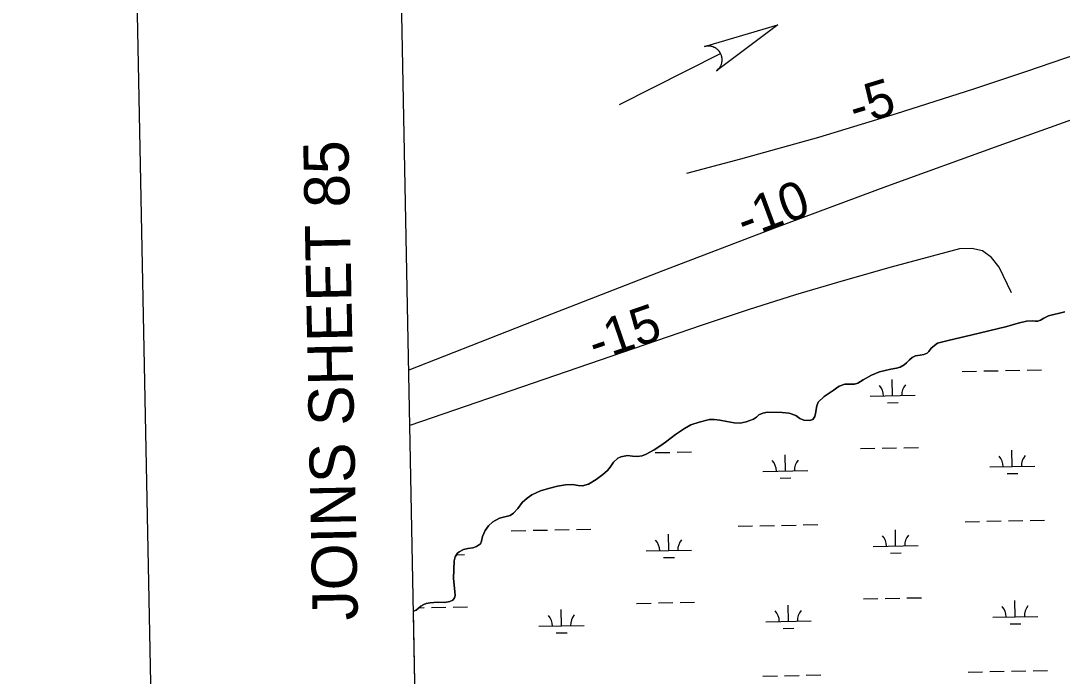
# Model space of a CAD drawing. Extents: x 3989314 to 4027622, y 243956 to 270014.
# Drawn here: x 3992659 to 3994963, y 253743 to 255194 of the extents above; entities that cross this region are included whole.
import ezdxf

# ---------------------------------------------------------------- set-up
doc = ezdxf.new("R2010")
doc.units = 0
for name, color, linetype in [('V-ANNO-SYMB', 7, 'Continuous'), ('V-ANNO-TEXT', 7, 'Continuous'), ('V-GRID-FRAM', 7, 'Continuous'), ('V-RIVR-EDGE', 7, 'Continuous'), ('V-STRM-FLOW', 7, 'Continuous'), ('V-TOPO-MINR', 7, 'Continuous'), ('V-TOPO-MINR-IDEN', 7, 'Continuous'), ('V-WETL-SWMP', 7, 'Continuous')]:
    doc.layers.add(name, color=color, linetype=linetype)

msp = doc.modelspace()

# ---------------------------------------------------------------- linework, layer by layer
at = {"layer": 'V-ANNO-SYMB'}
msp.add_lwpolyline([(3993116.1, 245218.5), (4026192.7, 245877.7), (4025736.1, 268789.7), (3992659.5, 268130.6), (3993116.1, 245218.5)], dxfattribs=at)
at = {"layer": 'V-GRID-FRAM'}
msp.add_lwpolyline([(3993261.4, 267575.2), (4025156.8, 268210.8), (4025527.1, 250031.9), (3993615.7, 249396), (3993261.4, 267575.2)], dxfattribs=at)
at = {"layer": 'V-RIVR-EDGE'}
for points in [[(3994968.3, 254550), (3994932.8, 254540.7), (3994922.1, 254535.7), (3994914.7, 254531.5), (3994909.2, 254529.1), (3994902.6, 254528.9), (3994897.1, 254529.5), (3994884.1, 254529.1), (3994865.7, 254524.3), (3994840.5, 254517.1), (3994761, 254498.4), (3994713.6, 254486.7), (3994687.2, 254480.5), (3994672.9, 254469.6), (3994667.4, 254461.6), (3994664.4, 254458.4), (3994656.7, 254455), (3994648.7, 254454), (3994638.6, 254452.2), (3994630.8, 254448.8)], [(3994630.8, 254448.8), (3994624.7, 254443.6), (3994618.2, 254436.6), (3994613.2, 254432.3), (3994604.1, 254427.3), (3994596.5, 254424.9), (3994583.6, 254423), (3994558.6, 254417.2), (3994541.3, 254409.4), (3994522.5, 254398.9), (3994510.8, 254391.9), (3994503, 254389.5), (3994491.5, 254389.4), (3994481.8, 254389.6), (3994469.1, 254385), (3994456.2, 254375.8), (3994436, 254362.7), (3994422.9, 254349.5), (3994420.1, 254342), (3994417.4, 254325.1), (3994415.4, 254318.1), (3994411.3, 254311.8), (3994403.5, 254309), (3994391.6, 254310.3), (3994382.8, 254313.9), (3994373.5, 254320.2), (3994359, 254325.5), (3994343.1, 254327.3), (3994311.1, 254327.6), (3994300.4, 254325.6), (3994291.8, 254321.8), (3994286.7, 254317), (3994279.7, 254312), (3994264.1, 254306.2), (3994250.6, 254303.6), (3994237.2, 254303.8), (3994221.1, 254306.9), (3994205.4, 254310.3), (3994193.1, 254311.8), (3994182.4, 254311.4), (3994159.8, 254305.8), (3994141.1, 254299.4), (3994127.2, 254291.4), (3994107.6, 254278.2), (3994088.5, 254263.7), (3994077.6, 254255.1), (3994060.6, 254244.1), (3994042.9, 254234.6), (3994033.6, 254231.4), (3994022.9, 254229.3), (3994012.5, 254230.3), (3994001.2, 254231.7), (3993986.9, 254229.2), (3993980, 254226.1), (3993970.4, 254217.1), (3993963.3, 254205.7), (3993957.2, 254198.4), (3993947.1, 254189.6), (3993932.2, 254179), (3993914.7, 254168.7), (3993902, 254164.7), (3993892.3, 254165.2), (3993879.4, 254167.4), (3993863.9, 254166.8), (3993846.2, 254164.1), (3993826.4, 254158.5), (3993808.9, 254153.3), (3993789.8, 254145.1), (3993779.1, 254137.7), (3993768, 254127.6), (3993758.9, 254114.8), (3993749, 254104.1), (3993741.5, 254099.3), (3993732.9, 254096.5), (3993718.4, 254093.1), (3993703.6, 254084.7), (3993693.8, 254076.3), (3993686.3, 254065.8), (3993680.8, 254052.5), (3993678.6, 254041.9), (3993675.9, 254036), (3993667.1, 254030.4), (3993659.2, 254027.4), (3993648.1, 254026), (3993638.6, 254023.8), (3993628.8, 254018.4), (3993625.1, 254015.4), (3993620.3, 254007.8), (3993618, 253998.7), (3993616.7, 253959.3), (3993619.5, 253930.7), (3993619.9, 253922.2), (3993618.8, 253917.2), (3993615, 253911.8), (3993608.6, 253908.7), (3993596.7, 253906.8), (3993580.8, 253907), (3993564.7, 253905.8)], [(3993564.7, 253905.8), (3993556, 253904.1), (3993550.8, 253902.1), (3993544.1, 253898.4), (3993533.8, 253889.6), (3993528.2, 253887)]]:
    msp.add_lwpolyline(points, dxfattribs=at)
at = {"layer": 'V-STRM-FLOW'}
msp.add_line((3993983.9, 255008.2), (3994207.3, 255121.2), dxfattribs=at)
msp.add_lwpolyline([(3994171.5, 255136.7), (3994333.7, 255185.1), (3994198.5, 255083.1), (3994200.9, 255085.1), (3994202.9, 255087.2), (3994203.7, 255088.1), (3994204.3, 255088.9), (3994205.1, 255089.9), (3994205.8, 255090.9), (3994206.3, 255091.8), (3994207, 255093.1), (3994207.7, 255094.5), (3994208.1, 255095.3), (3994208.5, 255096.3), (3994209, 255097.7), (3994209.4, 255098.8), (3994209.7, 255100), (3994209.9, 255100.8), (3994210, 255101.6), (3994210.2, 255102.7), (3994210.4, 255103.7), (3994210.5, 255104.7), (3994210.5, 255105.5), (3994210.6, 255106.7), (3994210.6, 255107.9), (3994210.6, 255108.9), (3994210.5, 255110), (3994210.4, 255110.9), (3994210.3, 255111.7), (3994210.2, 255112.4), (3994210, 255113.4), (3994209.8, 255114.4), (3994209.5, 255115.3), (3994209.3, 255116.3), (3994209, 255117.2), (3994208.6, 255118.1), (3994208.3, 255118.9), (3994207.9, 255120), (3994207.3, 255121.2), (3994207.1, 255121.5), (3994206.8, 255122.1), (3994206.5, 255122.7), (3994206.1, 255123.3), (3994205.7, 255123.9), (3994205.4, 255124.5), (3994204.9, 255125.1), (3994204.6, 255125.6), (3994204.1, 255126.2), (3994203.6, 255126.8), (3994203.3, 255127.2), (3994202.4, 255128.2), (3994201.9, 255128.7), (3994201.5, 255129.1), (3994201, 255129.7), (3994200.4, 255130.1), (3994199.8, 255130.6), (3994199.1, 255131.2), (3994198.5, 255131.7), (3994198, 255132.1), (3994197.5, 255132.4), (3994196.9, 255132.9), (3994196.3, 255133.2), (3994195.6, 255133.7), (3994194.9, 255134.1), (3994194.2, 255134.4), (3994193.3, 255134.9), (3994192.6, 255135.2), (3994191.8, 255135.5), (3994191.1, 255135.8), (3994190.5, 255136.1), (3994189.8, 255136.3), (3994188.8, 255136.6), (3994188.8, 255136.6), (3994188.2, 255136.8), (3994187.8, 255136.9), (3994187.1, 255137.1), (3994186.2, 255137.3), (3994185.6, 255137.4), (3994185, 255137.5), (3994184.2, 255137.6), (3994183.4, 255137.7), (3994182.9, 255137.8), (3994182.2, 255137.8), (3994181.2, 255137.9), (3994180.6, 255137.9), (3994180.2, 255137.9), (3994179.8, 255137.9), (3994179.3, 255137.9), (3994178.6, 255137.9), (3994178, 255137.8), (3994177.3, 255137.8), (3994176.7, 255137.7), (3994175.9, 255137.6), (3994175.4, 255137.5), (3994174.6, 255137.4), (3994173.7, 255137.2), (3994173, 255137.1), (3994172.5, 255136.9), (3994172, 255136.8), (3994171.7, 255136.7)], close=True, dxfattribs=at)
at = {"layer": 'V-TOPO-MINR'}
for points in [[(3995631.1, 255198.8), (3995607.7, 255193.4), (3995584.5, 255187.4), (3995561.5, 255180.4), (3995538.8, 255172.8), (3994822.5, 254916.8), (3994574, 254826.7), (3994326.2, 254734.9), (3994079.4, 254640.7), (3993833.1, 254544.8), (3993517.8, 254420.3)], [(3995216.6, 255200.1), (3995106.4, 255159), (3994995.5, 255119.7), (3994884.1, 255081.6), (3994766.6, 255042.5), (3994595.6, 254987.8), (3994423.9, 254935.7), (3994251, 254887.5), (3994131.6, 254856.1)], [(3994850.6, 254591.8), (3994823.4, 254648.6), (3994806.6, 254669.9), (3994786.8, 254684.8), (3994762.6, 254690.1), (3994735.5, 254689.1), (3994584.1, 254648.2), (3994478.4, 254618.5), (3994373, 254587.4), (3994268.3, 254554.1), (3994164.1, 254519.5), (3993520.2, 254298.3)]]:
    msp.add_lwpolyline(points, dxfattribs=at)
at = {"layer": 'V-WETL-SWMP'}
for p, q in [((3994932.8, 254540.7), (3994968.3, 254550)), ((3994840.5, 254517.1), (3994865.7, 254524.3)), ((3994865.7, 254524.3), (3994884.1, 254529.1)), ((3994884.1, 254529.1), (3994897.1, 254529.5)), ((3994897.1, 254529.5), (3994902.6, 254528.9)), ((3994902.6, 254528.9), (3994909.2, 254529.1)), ((3994909.2, 254529.1), (3994914.7, 254531.5)), ((3994914.7, 254531.5), (3994922.1, 254535.7)), ((3994922.1, 254535.7), (3994932.8, 254540.7)), ((3994761, 254498.4), (3994840.5, 254517.1)), ((3994672.9, 254469.6), (3994687.2, 254480.5)), ((3994687.2, 254480.5), (3994713.6, 254486.7)), ((3994713.6, 254486.7), (3994761, 254498.4)), ((3994656.6, 254455), (3994664.4, 254458.4)), ((3994664.4, 254458.4), (3994667.4, 254461.6)), ((3994667.4, 254461.6), (3994672.9, 254469.6)), ((3994604.1, 254427.3), (3994613.2, 254432.3)), ((3994613.2, 254432.3), (3994618.2, 254436.6)), ((3994618.2, 254436.6), (3994624.7, 254443.6)), ((3994624.7, 254443.6), (3994630.8, 254448.8)), ((3994630.8, 254448.8), (3994638.6, 254452.2)), ((3994638.6, 254452.2), (3994648.7, 254454)), ((3994648.7, 254454), (3994656.6, 254455)), ((3994522.5, 254398.9), (3994541.3, 254409.4)), ((3994541.3, 254409.4), (3994558.6, 254417.2)), ((3994558.6, 254417.2), (3994583.6, 254423)), ((3994583.6, 254423), (3994596.5, 254424.9)), ((3994596.5, 254424.9), (3994604.1, 254427.3)), ((3994741.3, 254417.9), (3994773.3, 254418.6)), ((3994789.3, 254418.9), (3994821.3, 254419.5)), ((3994837.3, 254419.8), (3994869.3, 254420.5)), ((3994885.3, 254420.8), (3994917.3, 254421.4)), ((3994469.1, 254385), (3994481.8, 254389.6)), ((3994481.8, 254389.6), (3994491.5, 254389.4)), ((3994491.5, 254389.4), (3994503, 254389.5)), ((3994503, 254389.5), (3994510.8, 254391.9)), ((3994510.8, 254391.9), (3994522.5, 254398.9)), ((3994587.7, 254364.1), (3994587, 254400.1)), ((3994436, 254362.7), (3994456.2, 254375.8)), ((3994456.2, 254375.8), (3994469.1, 254385)), ((3994537.8, 254363.1), (3994637.7, 254365.1)), ((3994417.4, 254325.1), (3994420.1, 254342)), ((3994420.1, 254342), (3994422.9, 254349.5)), ((3994422.9, 254349.5), (3994436, 254362.7)), ((3994576.1, 254348.4), (3994600, 254348.9)), ((3994279.7, 254312), (3994286.7, 254317)), ((3994286.7, 254317), (3994291.8, 254321.8)), ((3994291.8, 254321.8), (3994300.4, 254325.6)), ((3994300.4, 254325.6), (3994311.1, 254327.6)), ((3994311.1, 254327.6), (3994343.1, 254327.3)), ((3994343.1, 254327.3), (3994359, 254325.5)), ((3994359, 254325.5), (3994373.5, 254320.2)), ((3994373.5, 254320.2), (3994382.8, 254313.9)), ((3994411.3, 254311.8), (3994415.4, 254318.1)), ((3994415.4, 254318.1), (3994417.4, 254325.1)), ((3994127.2, 254291.4), (3994141.1, 254299.4)), ((3994141.1, 254299.4), (3994159.8, 254305.8)), ((3994159.8, 254305.8), (3994182.4, 254311.4)), ((3994182.4, 254311.4), (3994193.1, 254311.8)), ((3994193.1, 254311.8), (3994205.4, 254310.3)), ((3994205.4, 254310.3), (3994221.1, 254306.9)), ((3994221.1, 254306.9), (3994237.2, 254303.8)), ((3994237.2, 254303.8), (3994250.6, 254303.6)), ((3994250.6, 254303.6), (3994264.1, 254306.2)), ((3994264.1, 254306.2), (3994279.7, 254312)), ((3994382.8, 254313.9), (3994391.6, 254310.3)), ((3994391.6, 254310.3), (3994403.5, 254309)), ((3994403.5, 254309), (3994411.3, 254311.8)), ((3994088.5, 254263.7), (3994107.6, 254278.2)), ((3994107.6, 254278.2), (3994127.2, 254291.4)), ((3994060.6, 254244.1), (3994077.6, 254255.1)), ((3994077.6, 254255.1), (3994088.5, 254263.7)), ((3994516.6, 254247.2), (3994548.6, 254247.9)), ((3994564.6, 254248.2), (3994596.6, 254248.8)), ((3994612.6, 254249.1), (3994644.6, 254249.8)), ((3993970.4, 254217.1), (3993980, 254226.1)), ((3993980, 254226.1), (3993986.9, 254229.2)), ((3993986.9, 254229.2), (3994001.2, 254231.7)), ((3994001.2, 254231.7), (3994012.5, 254230.3)), ((3994012.5, 254230.3), (3994022.9, 254229.3)), ((3994022.9, 254229.3), (3994033.6, 254231.4)), ((3994033.6, 254231.4), (3994042.9, 254234.6)), ((3994042.9, 254234.6), (3994060.6, 254244.1)), ((3994062.8, 254238.2), (3994094.8, 254238.8)), ((3994110.8, 254239.1), (3994142.8, 254239.8)), ((3994350.5, 254197.5), (3994349.8, 254233.5)), ((3994852.4, 254207.5), (3994851.6, 254243.5)), ((3993957.2, 254198.4), (3993963.3, 254205.7)), ((3993963.3, 254205.7), (3993970.4, 254217.1)), ((3994802.4, 254206.5), (3994902.3, 254208.5)), ((3993914.7, 254168.7), (3993932.2, 254179)), ((3993932.2, 254179), (3993947.1, 254189.6)), ((3993947.1, 254189.6), (3993957.2, 254198.4)), ((3994300.6, 254196.5), (3994400.5, 254198.5)), ((3994338.9, 254181.8), (3994362.8, 254182.3)), ((3994840.7, 254191.8), (3994864.7, 254192.3)), ((3993808.9, 254153.3), (3993826.4, 254158.5)), ((3993826.4, 254158.5), (3993846.2, 254164.1)), ((3993846.2, 254164.1), (3993863.9, 254166.8)), ((3993863.9, 254166.8), (3993879.4, 254167.4)), ((3993879.4, 254167.4), (3993892.3, 254165.2)), ((3993892.3, 254165.2), (3993902, 254164.7)), ((3993902, 254164.7), (3993914.7, 254168.7)), ((3993768, 254127.6), (3993779.1, 254137.7)), ((3993779.1, 254137.7), (3993789.8, 254145.1)), ((3993789.8, 254145.1), (3993808.9, 254153.3)), ((3993749, 254104.1), (3993758.9, 254114.8)), ((3993758.9, 254114.8), (3993768, 254127.6)), ((3993703.6, 254084.7), (3993718.4, 254093.1)), ((3993718.4, 254093.1), (3993732.9, 254096.5)), ((3993732.9, 254096.5), (3993741.5, 254099.3)), ((3993741.5, 254099.3), (3993749, 254104.1)), ((3994795.9, 254086.3), (3994827.9, 254086.9)), ((3994843.9, 254087.2), (3994875.9, 254087.9)), ((3994891.9, 254088.2), (3994923.9, 254088.8)), ((3993680.8, 254052.5), (3993686.3, 254065.8)), ((3993686.3, 254065.8), (3993693.9, 254076.3)), ((3993693.9, 254076.3), (3993703.6, 254084.7)), ((3993744.3, 254065.3), (3993776.3, 254065.9)), ((3993792.3, 254066.3), (3993824.3, 254066.9)), ((3993840.3, 254067.2), (3993872.3, 254067.9)), ((3993888.3, 254068.2), (3993920.3, 254068.8)), ((3994246.1, 254075.3), (3994278.1, 254075.9)), ((3994294.1, 254076.3), (3994326.1, 254076.9)), ((3994342.1, 254077.2), (3994374.1, 254077.9)), ((3994390.1, 254078.2), (3994422.1, 254078.8)), ((3994594.4, 254031.5), (3994593.7, 254067.5)), ((3994747.9, 254085.3), (3994779.9, 254085.9)), ((3993675.9, 254036), (3993678.6, 254041.9)), ((3993678.6, 254041.9), (3993680.8, 254052.5)), ((3994092.6, 254021.5), (3994091.8, 254057.5)), ((3993625.1, 254015.4), (3993628.8, 254018.4)), ((3993628.8, 254018.4), (3993638.6, 254023.8)), ((3993638.6, 254023.8), (3993648.1, 254026)), ((3993648.1, 254026), (3993659.2, 254027.4)), ((3993659.2, 254027.4), (3993667.1, 254030.4)), ((3993667.1, 254030.4), (3993675.9, 254036)), ((3994042.6, 254020.5), (3994142.6, 254022.5)), ((3994544.4, 254030.5), (3994644.4, 254032.5)), ((3993616.7, 253959.3), (3993618, 253998.7)), ((3993618, 253998.7), (3993620.3, 254007.8)), ((3993620.3, 254007.8), (3993625.1, 254015.4)), ((3993623, 254012.1), (3993640.7, 254012.5)), ((3994080.9, 254005.8), (3994104.9, 254006.3)), ((3994582.7, 254015.8), (3994606.7, 254016.3)), ((3993619.5, 253930.7), (3993616.7, 253959.3)), ((3993619.9, 253922.2), (3993619.5, 253930.7)), ((3993550.8, 253902.2), (3993556, 253904.1)), ((3993556, 253904.1), (3993564.7, 253905.8)), ((3993564.7, 253905.8), (3993580.8, 253907)), ((3993580.8, 253907), (3993596.7, 253906.8)), ((3993596.7, 253906.8), (3993608.6, 253908.7)), ((3993608.6, 253908.7), (3993615, 253911.8)), ((3993615, 253911.8), (3993618.8, 253917.2)), ((3993618.8, 253917.2), (3993619.9, 253922.2)), ((3994021.5, 253904.6), (3994053.5, 253905.3)), ((3994069.5, 253905.6), (3994101.5, 253906.2)), ((3994117.5, 253906.5), (3994149.4, 253907.2)), ((3994523.3, 253914.6), (3994555.3, 253915.3)), ((3994571.3, 253915.6), (3994603.3, 253916.2)), ((3994619.3, 253916.5), (3994651.3, 253917.2)), ((3994859, 253874.9), (3994858.3, 253910.9)), ((3993528.2, 253887), (3993533.8, 253889.6)), ((3993534.2, 253577.5), (3993528.2, 253887)), ((3993533.8, 253889.6), (3993544.1, 253898.4)), ((3993540.2, 253895), (3993551.7, 253895.3)), ((3993544.1, 253898.4), (3993550.8, 253902.2)), ((3993567.7, 253895.6), (3993599.6, 253896.2)), ((3993615.6, 253896.5), (3993647.6, 253897.2)), ((3993855.4, 253854.9), (3993854.6, 253890.9)), ((3994357.2, 253864.9), (3994356.5, 253900.9)), ((3994307.2, 253863.9), (3994407.2, 253865.9)), ((3994809, 253873.9), (3994909, 253875.9)), ((3994847.3, 253859.2), (3994871.3, 253859.7)), ((3993805.4, 253853.9), (3993905.4, 253855.9)), ((3993843.7, 253839.2), (3993867.7, 253839.7)), ((3994345.5, 253849.2), (3994369.5, 253849.7)), ((3994300.7, 253743.7), (3994332.7, 253744.3)), ((3994348.7, 253744.6), (3994380.7, 253745.3)), ((3994396.7, 253745.6), (3994428.7, 253746.2)), ((3994754.6, 253752.7), (3994786.5, 253753.3)), ((3994802.5, 253753.7), (3994834.5, 253754.3)), ((3994850.5, 253754.6), (3994882.5, 253755.3)), ((3994898.5, 253755.6), (3994930.5, 253756.2))]:
    msp.add_line(p, q, dxfattribs=at)
for centre, start, end in [((3994532.5, 254363.5), 0.3699, 41.9135), ((3994643, 254365.7), 140.3699, 181.9135), ((3994797.1, 254206.9), 0.3699, 41.9135), ((3994907.6, 254209.1), 140.3699, 181.9135), ((3994295.3, 254196.9), 0.3699, 41.9135), ((3994405.8, 254199.1), 140.3699, 181.9135), ((3994037.3, 254020.9), 0.3699, 41.9135), ((3994147.8, 254023.1), 140.3699, 181.9135), ((3994539.1, 254030.9), 0.3699, 41.9135), ((3994649.6, 254033.1), 140.3699, 181.9135), ((3994301.9, 253864.3), 0.3699, 41.9135), ((3994412.4, 253866.5), 140.3699, 181.9135), ((3994803.7, 253874.3), 0.3699, 41.9135), ((3994914.2, 253876.5), 140.3699, 181.9135), ((3993800.1, 253854.2), 0.3699, 41.9135), ((3993910.6, 253856.5), 140.3699, 181.9135)]:
    msp.add_arc(centre, 35.2, start, end, dxfattribs=at)

# ---------------------------------------------------------------- texts
at = {"layer": 'V-ANNO-TEXT'}
msp.add_text('JOINS SHEET 85', height=100, rotation=91.1417, dxfattribs=at).set_placement((3993405.1, 253867.5))
at = {"layer": 'V-TOPO-MINR-IDEN'}
for s, rotation, p in [('-5', 16.8841, (3994505.3, 254960.4)), ('-10', 20.3243, (3994260.5, 254710.5)), ('-15', 18.9556, (3993930.6, 254439.3))]:
    msp.add_text(s, height=83, rotation=rotation, dxfattribs=at).set_placement(p)

doc.saveas('drawing.dxf')
